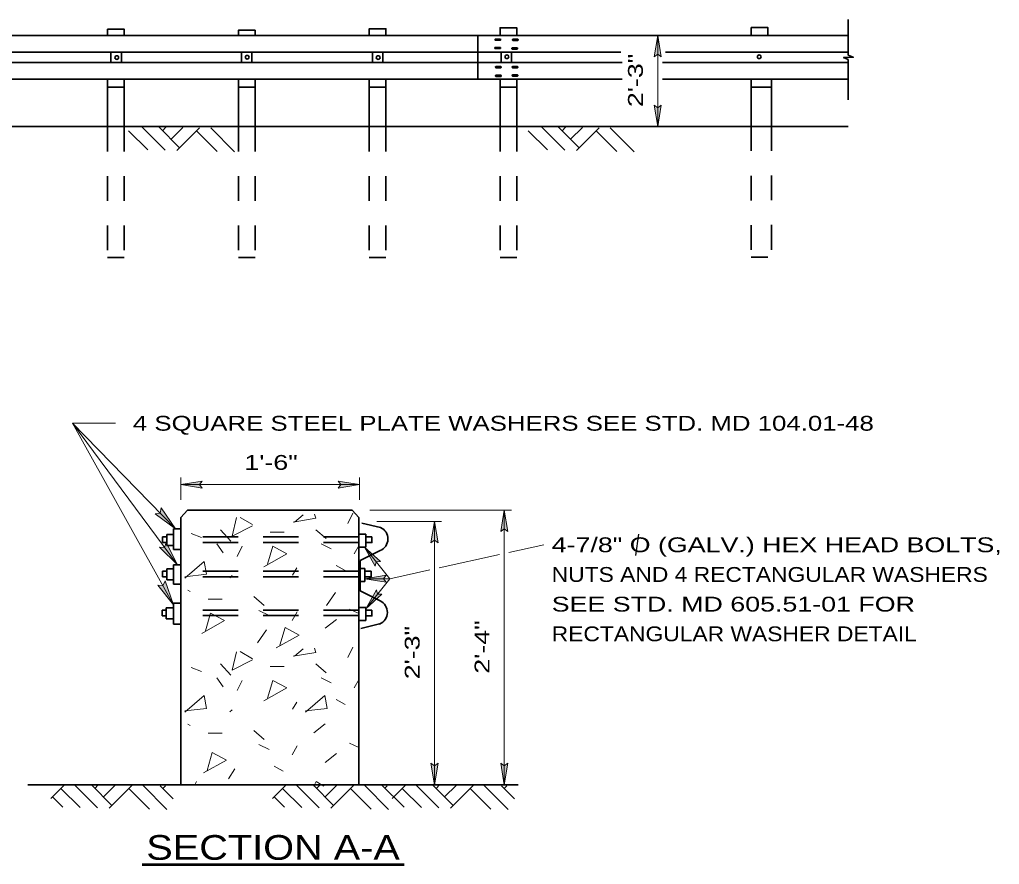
# Model space of a CAD drawing. Extents: x 49.7 to 60, y 209.2 to 216.1.
# Drawn here: x 56.086 to 60.049, y 209.259 to 212.675 of the extents above; entities that cross this region are included whole.
import ezdxf
from ezdxf.enums import TextEntityAlignment as Align

# ---------------------------------------------------------------- set-up
doc = ezdxf.new("R2010")
doc.units = 0
doc.header["$LTSCALE"] = 0.024
doc.linetypes.add('LONG_DASHED', pattern=[7.5, 6, -1.5])
doc.linetypes.add('MEDIUM_DASHED', pattern=[4.5, 3, -1.5])
for name, color, linetype, lineweight in [('1', 7, 'Continuous', 35), ('10', 7, 'Continuous', 13), ('12', 7, 'Continuous', 53), ('6', 7, 'Continuous', 13)]:
    doc.layers.add(name, color=color, linetype=linetype, lineweight=lineweight)

msp = doc.modelspace()

# ---------------------------------------------------------------- hatches: boundary and pattern name
at = {"layer": '10'}
for points in [[(58.68117, 212.52392), (58.66675, 212.61033), (58.65233, 212.52392), (58.66675, 212.53467)], [(58.68117, 212.3285), (58.66675, 212.24208), (58.65233, 212.3285), (58.66675, 212.31775)], [(56.82375, 210.80883), (56.73742, 210.79442), (56.82375, 210.78), (56.813, 210.79442)], [(57.46033, 210.79442), (57.374, 210.78), (57.38475, 210.79442), (57.374, 210.80883)], [(56.71633, 210.61625), (56.65792, 210.70017), (56.65467, 210.67942), (56.63383, 210.67667)], [(58.04633, 210.6915), (58.06075, 210.60508), (58.04633, 210.61592), (58.03192, 210.60508)], [(57.77842, 210.55917), (57.764, 210.64558), (57.74958, 210.55917), (57.764, 210.57)], [(56.72517, 210.47017), (56.6785, 210.56117), (56.67258, 210.541), (56.65158, 210.54108)], [(57.48033, 210.54142), (57.54583, 210.48325), (57.52792, 210.48258), (57.5235, 210.46517)], [(56.70833, 210.30875), (56.674, 210.405), (56.66542, 210.38583), (56.64458, 210.38867)], [(57.48267, 210.41425), (57.56908, 210.39983), (57.55825, 210.41425), (57.56908, 210.42858)], [(57.48625, 210.29292), (57.5515, 210.35142), (57.5335, 210.352), (57.529, 210.36942)], [(57.764, 209.65692), (57.77842, 209.66775), (57.764, 209.58133), (57.74958, 209.66775)], [(58.06075, 209.66775), (58.04633, 209.58133), (58.03192, 209.66775), (58.04633, 209.65692)]]:
    msp.add_hatch(color=256, dxfattribs=at).paths.add_polyline_path(points)

# ---------------------------------------------------------------- linework, layer by layer
at = {"layer": '1'}
for p, q in [((53.62417, 212.61033), (59.43725, 212.61033)), ((57.93925, 212.60917), (57.93925, 212.43433)), ((58.00983, 212.59608), (58.0305, 212.59608)), ((58.0305, 212.59108), (58.00983, 212.59108)), ((58.08067, 212.59525), (58.10125, 212.59525)), ((58.10125, 212.59025), (58.08067, 212.59025)), ((53.77083, 212.5425), (58.51725, 212.5425)), ((56.4555, 212.542), (56.4555, 212.50292)), ((56.49775, 212.54217), (56.49775, 212.50342)), ((56.98317, 212.54367), (56.98317, 212.50458)), ((57.02542, 212.54392), (57.02542, 212.50508)), ((57.51258, 212.542), (57.51258, 212.50292)), ((57.55483, 212.54217), (57.55483, 212.50342)), ((58.009, 212.5625), (58.02958, 212.5625)), ((58.02958, 212.5575), (58.009, 212.5575)), ((58.03358, 212.5425), (58.03358, 212.50183)), ((58.07575, 212.5425), (58.07575, 212.50183)), ((58.07808, 212.56083), (58.09875, 212.56083)), ((58.09875, 212.55583), (58.07808, 212.55583)), ((59.43725, 212.5425), (58.69775, 212.5425)), ((53.76975, 212.50183), (58.52367, 212.50183)), ((59.43725, 212.50183), (58.686, 212.50183)), ((58.0115, 212.48517), (58.03217, 212.48517)), ((58.03217, 212.48017), (58.0115, 212.48017)), ((58.07892, 212.48517), (58.09958, 212.48517)), ((58.09958, 212.48017), (58.07892, 212.48017)), ((53.62417, 212.43392), (58.52367, 212.43392)), ((56.44175, 212.24208), (56.44175, 212.43208)), ((56.5095, 212.24208), (56.5095, 212.43208)), ((56.97083, 212.24208), (56.97083, 212.43208)), ((57.03867, 212.24208), (57.03867, 212.43208)), ((57.5, 212.24208), (57.5, 212.43208)), ((57.56783, 212.24208), (57.56783, 212.43208)), ((58.01242, 212.44992), (58.033, 212.44992)), ((58.033, 212.44492), (58.01242, 212.44492)), ((58.02908, 212.24208), (58.02908, 212.43208)), ((58.07892, 212.45167), (58.09958, 212.45167)), ((58.09958, 212.44667), (58.07892, 212.44667)), ((58.09683, 212.24208), (58.09683, 212.43208)), ((59.43725, 212.43392), (58.686, 212.43392)), ((59.04508, 212.24358), (59.04508, 212.43392)), ((59.12642, 212.24442), (59.12642, 212.43433)), ((56.44175, 212.40117), (56.5095, 212.40117)), ((56.97083, 212.40117), (57.03867, 212.40117)), ((57.5, 212.40117), (57.56783, 212.40117)), ((58.02908, 212.40117), (58.09683, 212.40117)), ((59.12642, 212.40117), (59.04508, 212.40117)), ((54.20317, 212.24208), (59.437, 212.24208)), ((56.765, 210.6915), (56.73833, 210.6615)), ((56.765, 210.6915), (57.43092, 210.6915)), ((57.43092, 210.6915), (57.45842, 210.6615)), ((56.73833, 209.58133), (56.73833, 210.6615)), ((57.45842, 209.58133), (57.45842, 210.6615)), ((57.47017, 210.639), (57.546, 210.62142)), ((56.70775, 210.59258), (56.681, 210.59258)), ((56.681, 210.59258), (56.681, 210.54892)), ((56.73833, 210.61625), (56.70833, 210.61625)), ((56.70833, 210.53233), (56.70833, 210.61625)), ((57.45842, 210.59458), (57.48625, 210.59458)), ((57.48625, 210.59458), (57.48625, 210.54142)), ((56.681, 210.58317), (56.66392, 210.58317)), ((56.66392, 210.58317), (56.66392, 210.56025)), ((56.68108, 210.56025), (56.66392, 210.56025)), ((57.511, 210.58325), (57.48625, 210.58325)), ((56.70833, 210.54892), (56.681, 210.54892)), ((56.70833, 210.53233), (56.73833, 210.53233)), ((57.45842, 210.54142), (57.48625, 210.54142)), ((56.681, 210.44442), (56.66392, 210.44442)), ((56.66392, 210.44442), (56.66392, 210.42158)), ((56.70833, 210.45383), (56.681, 210.45383)), ((56.681, 210.45383), (56.681, 210.41017)), ((56.70833, 210.47017), (56.73833, 210.47017)), ((56.70833, 210.47017), (56.70833, 210.3915)), ((57.46317, 210.45575), (57.48267, 210.45575)), ((57.48267, 210.45575), (57.48267, 210.4025)), ((57.50742, 210.44442), (57.48267, 210.44442)), ((56.681, 210.42158), (56.66392, 210.42158)), ((56.70833, 210.41017), (56.681, 210.41017)), ((56.70833, 210.3915), (56.73833, 210.3915)), ((57.46317, 210.40258), (57.48267, 210.40258)), ((56.70833, 210.31475), (56.73833, 210.31475)), ((56.70833, 210.31475), (56.70833, 210.23083)), ((56.67908, 210.28658), (56.662, 210.28658)), ((56.662, 210.28658), (56.662, 210.26375)), ((56.70833, 210.29608), (56.67908, 210.29608)), ((56.67908, 210.29608), (56.67908, 210.25233)), ((57.45842, 210.298), (57.48625, 210.298)), ((57.48625, 210.298), (57.48625, 210.24475)), ((57.511, 210.28658), (57.48625, 210.28658)), ((56.67917, 210.26375), (56.662, 210.26375)), ((56.70833, 210.25233), (56.67908, 210.25233)), ((57.45842, 210.24483), (57.48625, 210.24483)), ((56.70833, 210.23083), (56.73833, 210.23083)), ((57.54158, 210.23108), (57.46575, 210.2135)), ((58.1025, 209.58133), (56.11925, 209.58133))]:
    msp.add_line(p, q, dxfattribs=at)
at = {"layer": '1', "linetype": 'MEDIUM_DASHED'}
for p, q in [((56.44175, 212.24208), (56.44175, 211.713)), ((56.5095, 212.24208), (56.5095, 211.713)), ((56.97083, 212.24208), (56.97083, 211.713)), ((57.03867, 212.24208), (57.03867, 211.713)), ((57.5, 212.24208), (57.5, 211.713)), ((57.56783, 212.24208), (57.56783, 211.713)), ((58.02908, 212.24208), (58.02908, 211.713)), ((58.09683, 212.24208), (58.09683, 211.713)), ((59.04508, 212.24358), (59.04508, 211.7145)), ((59.12642, 212.24442), (59.12642, 211.71533)), ((56.44175, 211.713), (56.5095, 211.713)), ((56.97083, 211.713), (57.03867, 211.713)), ((57.5, 211.713), (57.56783, 211.713)), ((58.02908, 211.713), (58.09683, 211.713)), ((59.04508, 211.7145), (59.11283, 211.7145))]:
    msp.add_line(p, q, dxfattribs=at)
at = {"layer": '1', "linetype": 'LONG_DASHED'}
for p, q in [((57.45842, 210.58317), (56.73833, 210.58317)), ((57.45842, 210.56025), (56.73833, 210.56025)), ((57.45842, 210.44442), (56.73833, 210.44442)), ((57.45842, 210.42158), (56.73833, 210.42158)), ((57.45842, 210.28658), (56.73925, 210.28658)), ((57.45842, 210.26475), (56.73925, 210.26475))]:
    msp.add_line(p, q, dxfattribs=at)
at = {"layer": '1'}
for points in [[(56.44175, 212.61208), (56.44175, 212.63558), (56.5095, 212.63558), (56.5095, 212.61208)], [(56.97083, 212.61075), (56.97083, 212.632), (57.03867, 212.632), (57.03867, 212.61092)], [(57.5, 212.61075), (57.5, 212.63783), (57.56783, 212.63783), (57.56783, 212.61075)], [(58.02908, 212.60958), (58.02908, 212.64192), (58.09683, 212.64192), (58.09683, 212.60958)], [(59.04508, 212.61033), (59.04508, 212.64258), (59.11283, 212.64258), (59.11283, 212.61033)], [(57.48625, 210.56042), (57.511, 210.56042), (57.511, 210.58325)], [(57.54375, 210.52808), (57.46317, 210.48733), (57.46317, 210.36517), (57.54375, 210.32442)], [(57.48267, 210.42158), (57.50742, 210.42158), (57.50742, 210.44442)], [(57.48625, 210.26383), (57.511, 210.26383), (57.511, 210.28658)]]:
    msp.add_lwpolyline(points, dxfattribs=at)
for centre in [(58.05705, 212.5244), (59.07734, 212.5244), (56.479, 212.52104), (57.00668, 212.52272), (57.53609, 212.52104)]:
    msp.add_circle(centre, 0.00749, dxfattribs=at)
for centre, radius, start, end in [((58.01113, 212.59355), 0.00283, 117.91346, 242.08653), ((58.02909, 212.59355), 0.00283, 297.91346, 62.08653), ((58.08195, 212.59271), 0.00283, 117.91346, 242.08653), ((58.0999, 212.59271), 0.00283, 297.91346, 62.08653), ((58.01029, 212.55994), 0.00283, 117.91346, 242.08653), ((58.02825, 212.55994), 0.00283, 297.91346, 62.08653), ((58.07938, 212.55826), 0.00283, 117.91346, 242.08653), ((58.09734, 212.55826), 0.00283, 297.91346, 62.08653), ((58.01281, 212.48265), 0.00283, 117.91346, 242.08653), ((58.03077, 212.48265), 0.00283, 297.91346, 62.08653), ((58.08022, 212.48265), 0.00283, 117.91346, 242.08653), ((58.09818, 212.48265), 0.00283, 297.91346, 62.08653), ((58.01365, 212.4474), 0.00283, 117.91346, 242.08653), ((58.03161, 212.4474), 0.00283, 297.91346, 62.08653), ((58.08022, 212.44908), 0.00283, 117.91346, 242.08653), ((58.09818, 212.44908), 0.00283, 297.91346, 62.08653), ((57.5249, 210.57514), 0.05077, 291.78198, 65.51256), ((57.5227, 210.27818), 0.05077, 291.78198, 65.51256)]:
    msp.add_arc(centre, radius, start, end, dxfattribs=at)
at = {"layer": '10', "lineweight": 35}
for p, q in [((59.43725, 212.67475), (59.43725, 212.53058)), ((59.43725, 212.35033), (59.43725, 212.513))]:
    msp.add_line(p, q, dxfattribs=at)
at = {"layer": '10'}
for p, q in [((58.65233, 212.52392), (58.66675, 212.61033)), ((58.66675, 212.24208), (58.66675, 212.61033)), ((58.68117, 212.52392), (58.66675, 212.61033)), ((58.65233, 212.52392), (58.66675, 212.53467)), ((58.68117, 212.52392), (58.66675, 212.53467)), ((58.65233, 212.3285), (58.66675, 212.24208)), ((58.65233, 212.3285), (58.66675, 212.31775)), ((58.68117, 212.3285), (58.66675, 212.24208)), ((58.68117, 212.3285), (58.66675, 212.31775)), ((56.474, 211.04308), (56.29975, 211.04308)), ((56.29975, 211.04308), (56.70833, 210.30875)), ((56.29975, 211.04308), (56.72517, 210.47017)), ((56.29975, 211.04308), (56.71633, 210.61625)), ((56.73742, 210.7335), (56.73742, 210.82317)), ((56.82375, 210.80883), (56.73742, 210.79442)), ((56.73742, 210.79442), (57.46033, 210.79442)), ((56.82375, 210.78), (56.73742, 210.79442)), ((56.82375, 210.80883), (56.813, 210.79442)), ((56.82375, 210.78), (56.813, 210.79442)), ((57.374, 210.80883), (57.46033, 210.79442)), ((57.374, 210.80883), (57.38475, 210.79442)), ((57.374, 210.78), (57.46033, 210.79442)), ((57.374, 210.78), (57.38475, 210.79442)), ((57.46033, 210.7335), (57.46033, 210.82317)), ((56.63383, 210.67667), (56.65467, 210.67942)), ((56.63383, 210.67667), (56.71633, 210.61625)), ((56.65792, 210.70017), (56.65467, 210.67942)), ((56.65792, 210.70017), (56.71633, 210.61625)), ((57.50292, 210.6915), (58.07517, 210.6915)), ((58.03192, 210.60508), (58.04633, 210.6915)), ((58.06075, 210.60508), (58.04633, 210.6915)), ((58.04633, 210.6915), (58.04633, 209.58133)), ((57.53017, 210.64592), (57.79275, 210.64592)), ((57.74958, 210.55917), (57.764, 210.64558)), ((57.77842, 210.55917), (57.764, 210.64558)), ((57.764, 210.64558), (57.764, 209.58133)), ((58.03192, 210.60508), (58.04633, 210.61592)), ((58.06075, 210.60508), (58.04633, 210.61592)), ((56.6785, 210.56117), (56.67258, 210.541)), ((56.6785, 210.56117), (56.72517, 210.47017)), ((57.74958, 210.55917), (57.764, 210.57)), ((57.77842, 210.55917), (57.764, 210.57)), ((58.20567, 210.55142), (58.06467, 210.52033)), ((56.65158, 210.54108), (56.72517, 210.47017)), ((56.65158, 210.54108), (56.67258, 210.541)), ((57.5235, 210.46517), (57.48033, 210.54142)), ((57.54583, 210.48325), (57.48033, 210.54142)), ((57.58325, 210.41425), (57.48033, 210.54142)), ((58.02717, 210.512), (57.783, 210.45825)), ((57.5235, 210.46517), (57.52792, 210.48258)), ((57.54583, 210.48325), (57.52792, 210.48258)), ((57.58325, 210.41425), (57.74542, 210.44992)), ((56.674, 210.405), (56.66542, 210.38583)), ((56.674, 210.405), (56.70833, 210.30875)), ((57.56908, 210.42858), (57.48267, 210.41425)), ((57.56908, 210.39983), (57.48267, 210.41425)), ((57.58325, 210.41425), (57.48267, 210.41425)), ((57.58325, 210.41425), (57.48625, 210.29292)), ((57.56908, 210.42858), (57.55825, 210.41425)), ((57.56908, 210.39983), (57.55825, 210.41425)), ((56.64458, 210.38867), (56.70833, 210.30875)), ((56.64458, 210.38867), (56.66542, 210.38583)), ((57.529, 210.36942), (57.48625, 210.29292)), ((57.529, 210.36942), (57.5335, 210.352)), ((57.5515, 210.35142), (57.5335, 210.352)), ((57.5515, 210.35142), (57.48625, 210.29292)), ((57.74958, 209.66775), (57.764, 209.58133)), ((57.74958, 209.66775), (57.764, 209.65692)), ((57.77842, 209.66775), (57.764, 209.58133)), ((57.77842, 209.66775), (57.764, 209.65692)), ((58.03192, 209.66775), (58.04633, 209.58133)), ((58.03192, 209.66775), (58.04633, 209.65692)), ((58.06075, 209.66775), (58.04633, 209.58133)), ((58.06075, 209.66775), (58.04633, 209.65692))]:
    msp.add_line(p, q, dxfattribs=at)
for points in [[(58.68117, 212.52392), (58.66675, 212.61033), (58.65233, 212.52392), (58.66675, 212.53467)], [(58.68117, 212.3285), (58.66675, 212.24208), (58.65233, 212.3285), (58.66675, 212.31775)], [(56.82375, 210.80883), (56.73742, 210.79442), (56.82375, 210.78), (56.813, 210.79442)], [(57.46033, 210.79442), (57.374, 210.78), (57.38475, 210.79442), (57.374, 210.80883)], [(56.71633, 210.61625), (56.65792, 210.70017), (56.65467, 210.67942), (56.63383, 210.67667)], [(58.04633, 210.6915), (58.06075, 210.60508), (58.04633, 210.61592), (58.03192, 210.60508)], [(57.77842, 210.55917), (57.764, 210.64558), (57.74958, 210.55917), (57.764, 210.57)], [(56.72517, 210.47017), (56.6785, 210.56117), (56.67258, 210.541), (56.65158, 210.54108)], [(57.48033, 210.54142), (57.54583, 210.48325), (57.52792, 210.48258), (57.5235, 210.46517)], [(56.70833, 210.30875), (56.674, 210.405), (56.66542, 210.38583), (56.64458, 210.38867)], [(57.48267, 210.41425), (57.56908, 210.39983), (57.55825, 210.41425), (57.56908, 210.42858)], [(57.48625, 210.29292), (57.5515, 210.35142), (57.5335, 210.352), (57.529, 210.36942)], [(57.764, 209.65692), (57.77842, 209.66775), (57.764, 209.58133), (57.74958, 209.66775)], [(58.06075, 209.66775), (58.04633, 209.58133), (58.03192, 209.66775), (58.04633, 209.65692)]]:
    msp.add_lwpolyline(points, close=True, dxfattribs=at)
at = {"layer": '10', "lineweight": 35}
msp.add_lwpolyline([(59.43767, 212.531), (59.45767, 212.52225), (59.41867, 212.522), (59.43767, 212.51292)], dxfattribs=at)
at = {"layer": '12', "lineweight": 25}
msp.add_line((58.57792, 210.50792), (58.59008, 210.59492), dxfattribs=at)
at = {"layer": '12'}
msp.add_line((56.58142, 209.25908), (57.64117, 209.25908), dxfattribs=at)
at = {"layer": '6'}
for p, q in [((56.60442, 212.14792), (56.52658, 212.22558)), ((56.67458, 212.14642), (56.58025, 212.24075)), ((56.73275, 212.15692), (56.64992, 212.23958)), ((56.66408, 212.22558), (56.67792, 212.23942)), ((56.69842, 212.19108), (56.74592, 212.23842)), ((56.73275, 212.15692), (56.81375, 212.23758)), ((56.88492, 212.14208), (56.80158, 212.22558)), ((56.95492, 212.14075), (56.85875, 212.23692)), ((58.22067, 212.14792), (58.14283, 212.22558)), ((58.29083, 212.14642), (58.1965, 212.24075)), ((58.349, 212.15692), (58.26617, 212.23958)), ((58.28033, 212.22558), (58.29417, 212.23942)), ((58.31467, 212.19108), (58.36217, 212.23842)), ((58.349, 212.15692), (58.43, 212.23758)), ((58.50117, 212.14208), (58.41783, 212.22558)), ((58.57117, 212.14075), (58.475, 212.23692)), ((56.72142, 212.14542), (56.73275, 212.15692)), ((58.33767, 212.14542), (58.349, 212.15692)), ((57.23225, 210.67308), (57.19725, 210.64308)), ((57.41342, 210.63775), (57.43408, 210.67908)), ((56.97758, 210.66175), (57.02742, 210.63275)), ((56.78042, 210.59675), (56.82142, 210.58108)), ((56.89875, 210.61208), (56.93992, 210.56575)), ((57.09942, 210.60175), (57.15608, 210.60175)), ((57.28458, 210.61208), (57.32592, 210.57608)), ((56.88325, 210.55542), (56.90908, 210.51942)), ((57.30525, 210.55542), (57.34642, 210.53492)), ((57.43908, 210.51442), (57.45975, 210.55025)), ((56.98608, 210.54525), (56.96558, 210.50408)), ((57.18975, 210.42892), (57.20758, 210.45758)), ((57.36692, 210.46792), (57.40308, 210.44742)), ((56.94508, 210.42675), (56.93658, 210.41775)), ((56.76675, 210.36825), (56.77625, 210.36275)), ((57.36308, 210.35775), (57.32708, 210.30625)), ((56.84825, 210.33208), (56.90475, 210.33208)), ((57.03342, 210.34242), (57.07475, 210.30625)), ((57.05408, 210.28575), (57.09525, 210.26508)), ((57.18792, 210.24458), (57.20858, 210.28058)), ((57.41958, 210.29075), (57.45558, 210.27525)), ((57.36792, 210.24975), (57.32175, 210.21375)), ((57.08475, 210.207), (57.04875, 210.1555)), ((56.97758, 210.11967), (57.02742, 210.09067)), ((57.23225, 210.131), (57.19725, 210.101)), ((57.41342, 210.09567), (57.43408, 210.137)), ((56.78042, 210.05467), (56.82142, 210.039)), ((56.89875, 210.07), (56.93992, 210.02367)), ((57.09942, 210.05967), (57.15608, 210.05967)), ((57.28458, 210.07), (57.32592, 210.034)), ((56.88325, 210.01333), (56.90908, 209.97733)), ((56.98608, 210.00317), (56.96558, 209.962)), ((57.30525, 210.01333), (57.34642, 209.99283)), ((57.43908, 209.97233), (57.45975, 210.00817)), ((57.36692, 209.92583), (57.40308, 209.90533)), ((56.94508, 209.88467), (56.93658, 209.87567)), ((57.18975, 209.88683), (57.20758, 209.9155)), ((56.76675, 209.82617), (56.77625, 209.82067)), ((57.03342, 209.80033), (57.07475, 209.76417)), ((57.32242, 209.82733), (57.27625, 209.79133)), ((56.84825, 209.79), (56.90475, 209.79)), ((57.05408, 209.74367), (57.09525, 209.723)), ((57.18792, 209.7025), (57.20858, 209.7385)), ((57.41958, 209.74867), (57.45558, 209.73317)), ((57.36792, 209.70767), (57.32175, 209.67167)), ((56.93058, 209.60467), (56.95642, 209.64583)), ((57.11592, 209.656), (57.15175, 209.63567)), ((56.2125, 209.52583), (56.26867, 209.58167)), ((56.33083, 209.48867), (56.253, 209.56633)), ((56.401, 209.48717), (56.30667, 209.5815)), ((56.45917, 209.49767), (56.37633, 209.58033)), ((56.3905, 209.56633), (56.40433, 209.58017)), ((56.42483, 209.53183), (56.47233, 209.57917)), ((56.45917, 209.49767), (56.54017, 209.57833)), ((56.61133, 209.48283), (56.528, 209.56633)), ((56.68133, 209.4815), (56.58517, 209.57767)), ((56.70683, 209.52483), (56.655, 209.57683)), ((56.6655, 209.56633), (56.67567, 209.5765)), ((56.80192, 209.59433), (56.79608, 209.583)), ((57.10917, 209.52583), (57.16533, 209.58167)), ((57.2275, 209.48867), (57.14967, 209.56633)), ((57.29767, 209.48717), (57.20333, 209.5815)), ((57.35583, 209.49767), (57.273, 209.58033)), ((57.28717, 209.56633), (57.301, 209.58017)), ((57.3215, 209.53183), (57.369, 209.57917)), ((57.35583, 209.49767), (57.43683, 209.57833)), ((57.508, 209.48283), (57.42467, 209.56633)), ((57.578, 209.4815), (57.48183, 209.57767)), ((57.64092, 209.49), (57.55, 209.58092)), ((57.56217, 209.56633), (57.57233, 209.5765)), ((57.59275, 209.52583), (57.64892, 209.58167)), ((57.71108, 209.48867), (57.63325, 209.56633)), ((57.78125, 209.48717), (57.68692, 209.5815)), ((57.83942, 209.49767), (57.75658, 209.58033)), ((57.77075, 209.56633), (57.78458, 209.58017)), ((57.80508, 209.53183), (57.85258, 209.57917)), ((57.83942, 209.49767), (57.92042, 209.57833)), ((57.99158, 209.48283), (57.90825, 209.56633)), ((58.06158, 209.4815), (57.96542, 209.57767)), ((58.08708, 209.52483), (58.03525, 209.57683)), ((58.04575, 209.56633), (58.05592, 209.5765)), ((56.26067, 209.49), (56.21883, 209.53183)), ((57.15733, 209.49), (57.1155, 209.53183)), ((56.44783, 209.48617), (56.45917, 209.49767)), ((57.3445, 209.48617), (57.35583, 209.49767)), ((57.82808, 209.48617), (57.83942, 209.49767))]:
    msp.add_line(p, q, dxfattribs=at)
for points in [[(57.19208, 210.64308), (57.28458, 210.65842), (57.27908, 210.67508)], [(57.02742, 210.62758), (56.94508, 210.58642), (56.96375, 210.66125)], [(57.07375, 210.46275), (57.16625, 210.51442), (57.10975, 210.54525), (57.08908, 210.47308)], [(56.75458, 210.42175), (56.84192, 210.43192), (56.83175, 210.48342), (56.75458, 210.41658)], [(56.82242, 210.19308), (56.91525, 210.24458), (56.85858, 210.27525), (56.83808, 210.20325)], [(57.12342, 210.13492), (57.21625, 210.18642), (57.15958, 210.21708), (57.13908, 210.14508)], [(57.02742, 210.0855), (56.94508, 210.04433), (56.96375, 210.11917)], [(57.19208, 210.101), (57.28458, 210.11633), (57.27908, 210.133)], [(57.07375, 209.92067), (57.16625, 209.97233), (57.10975, 210.00317), (57.08908, 209.931)], [(56.75458, 209.87967), (56.84192, 209.88983), (56.83175, 209.94133), (56.75458, 209.8745)], [(57.24283, 209.87967), (57.33017, 209.88983), (57.32, 209.94133), (57.24283, 209.8745)], [(56.82925, 209.62875), (56.92208, 209.68025), (56.86542, 209.71092), (56.84492, 209.63892)], [(57.27575, 209.57583), (57.28575, 209.59433), (57.31658, 209.57533)]]:
    msp.add_lwpolyline(points, dxfattribs=at)

# ---------------------------------------------------------------- texts
at = {"layer": '12', "width": 1.35}
for s, p in [('2\'-3"', (58.60667, 212.42883)), ('2\'-4"', (57.98625, 210.138)), ('2\'-3"', (57.70383, 210.11533))]:
    msp.add_text(s, height=0.06001, rotation=90, dxfattribs=at).set_placement(p, align=Align.CENTER)
at = {"layer": '12'}
for s, height, width, p in [('4 SQUARE STEEL PLATE WASHERS SEE STD. MD 104.01-48', 0.06, 1.3, (56.54408, 211.01258)), ('4-7/8" O (GALV.) HEX HEAD BOLTS,', 0.06001, 1.35, (58.23808, 210.52133)), ('NUTS AND 4 RECTANGULAR WASHERS', 0.06001, 1.15, (58.23808, 210.40133)), ('SEE STD. MD 605.51-01 FOR', 0.06001, 1.35, (58.23808, 210.28133)), ('RECTANGULAR WASHER DETAIL', 0.06001, 1.15, (58.23808, 210.16125))]:
    msp.add_text(s, height=height, dxfattribs=dict(at, width=width)).set_placement(p)
for s, height, width, p in [('1\'-6"', 0.06001, 1.35, (57.10296, 210.85433)), ('SECTION A-A', 0.1, 1.2, (57.11113, 209.27767))]:
    msp.add_text(s, height=height, dxfattribs=dict(at, width=width)).set_placement(p, align=Align.CENTER)

doc.saveas('drawing.dxf')
